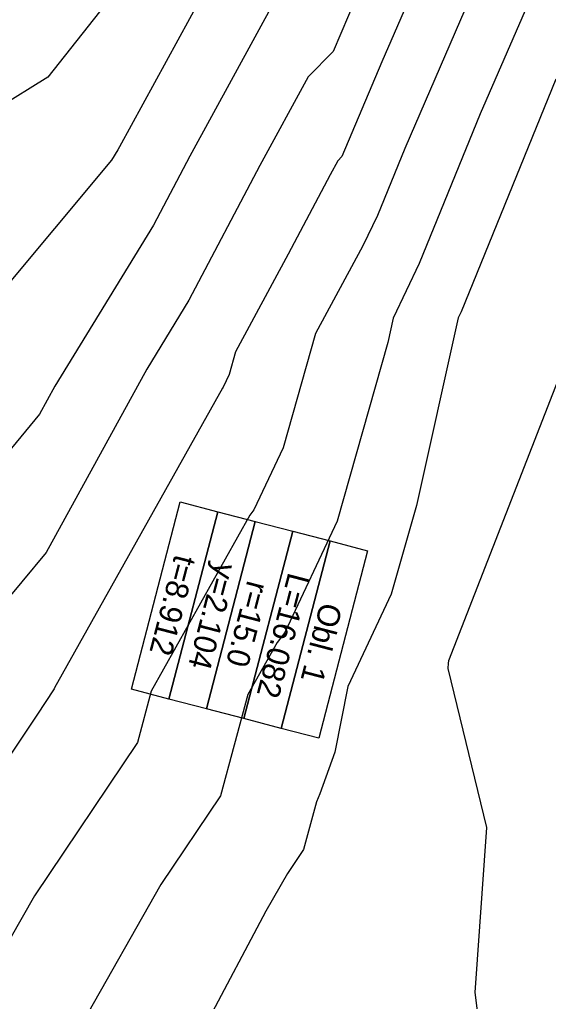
# Model space of a CAD drawing. Extents: x -549394 to -546608, y -1037055 to -1033629.
# Drawn here: x -547815.5 to -547733.5, y -1034670.8 to -1034518.7 of the extents above; entities that cross this region are included whole.
import ezdxf

# ---------------------------------------------------------------- set-up
doc = ezdxf.new("R2010")
doc.units = 0
for name, color, linetype in [('hlavni_vrst', 7, 'Continuous'), ('norm_vrst', 7, 'Continuous'), ('x_popis_oblouky_C211', 7, 'Continuous')]:
    doc.layers.add(name, color=color, linetype=linetype)

msp = doc.modelspace()

# ---------------------------------------------------------------- linework, layer by layer
at = {"layer": 'hlavni_vrst'}
for p, q in [((-547737, -1034495.44), (-547755.79, -1034538.71)), ((-547793.79, -1034505.78), (-547811.09, -1034527.65)), ((-547811.09, -1034527.65), (-547820.62, -1034533.57)), ((-547755.79, -1034538.71), (-547760.02, -1034549.09)), ((-547760.02, -1034549.09), (-547762.25, -1034553.76)), ((-547762.25, -1034553.76), (-547769.61, -1034567.38)), ((-547769.61, -1034567.38), (-547774.62, -1034585.07)), ((-547774.62, -1034585.07), (-547779.14, -1034594.65)), ((-547779.14, -1034594.65), (-547779.8, -1034595.52)), ((-547779.8, -1034595.52), (-547795.06, -1034622.76)), ((-547795.06, -1034622.76), (-547797.21, -1034630.7)), ((-547797.21, -1034630.7), (-547813.16, -1034654.45)), ((-547813.16, -1034654.45), (-547828.03, -1034680.56))]:
    msp.add_line(p, q, dxfattribs=at)
at = {"layer": 'norm_vrst'}
for p, q in [((-547747.6, -1034478.05), (-547766.85, -1034523.7)), ((-547741.45, -1034484.11), (-547759.32, -1034525.27)), ((-547779.89, -1034501.69), (-547799.97, -1034538.43)), ((-547732.55, -1034506.77), (-547744.08, -1034533.33)), ((-547775.31, -1034514.66), (-547789.09, -1034539.88)), ((-547766.85, -1034523.7), (-547770.72, -1034527.63)), ((-547759.32, -1034525.27), (-547765.52, -1034539.97)), ((-547770.72, -1034527.63), (-547778.21, -1034541.33)), ((-547732.38, -1034527.95), (-547747.04, -1034563.99)), ((-547744.08, -1034533.33), (-547753.53, -1034556.54)), ((-547799.97, -1034538.43), (-547800.23, -1034538.94)), ((-547800.23, -1034538.94), (-547801.2, -1034540.52)), ((-547789.09, -1034539.88), (-547794.73, -1034550.56)), ((-547765.52, -1034539.97), (-547766.14, -1034540.6)), ((-547801.2, -1034540.52), (-547820.19, -1034563.23)), ((-547778.21, -1034541.33), (-547789.22, -1034562.18)), ((-547766.14, -1034540.6), (-547767.34, -1034542.78)), ((-547767.34, -1034542.78), (-547773.83, -1034555.08)), ((-547794.73, -1034550.56), (-547809.98, -1034575.52)), ((-547773.83, -1034555.08), (-547781.99, -1034570.2)), ((-547753.53, -1034556.54), (-547757.57, -1034564.98)), ((-547789.22, -1034562.18), (-547795.76, -1034572.88)), ((-547727.2, -1034562.14), (-547749.02, -1034618.05)), ((-547747.04, -1034563.99), (-547747.51, -1034564.96)), ((-547757.57, -1034564.98), (-547758.41, -1034568.77)), ((-547747.51, -1034564.96), (-547753.98, -1034594)), ((-547758.41, -1034568.77), (-547766.25, -1034596.41)), ((-547781.99, -1034570.2), (-547783, -1034573.73)), ((-547795.76, -1034572.88), (-547811.34, -1034601.27)), ((-547783, -1034573.73), (-547783.9, -1034575.65)), ((-547809.98, -1034575.52), (-547812.36, -1034579.85)), ((-547784.03, -1034575.82), (-547810.04, -1034622.26)), ((-547783.9, -1034575.65), (-547784.03, -1034575.82)), ((-547812.36, -1034579.85), (-547833.3, -1034605.08)), ((-547753.98, -1034594), (-547757.88, -1034607.75)), ((-547766.25, -1034596.41), (-547774.38, -1034613.65)), ((-547811.34, -1034601.27), (-547821.7, -1034613.75)), ((-547757.88, -1034607.75), (-547764.62, -1034622.04)), ((-547774.38, -1034613.65), (-547775.57, -1034615.21)), ((-547775.57, -1034615.21), (-547780.08, -1034623.27)), ((-547749.07, -1034618.45), (-547749.08, -1034619.24)), ((-547749.08, -1034619.24), (-547743.1, -1034643.88)), ((-547749.02, -1034618.05), (-547749.07, -1034618.45)), ((-547810.04, -1034622.26), (-547810.08, -1034622.42)), ((-547764.62, -1034622.04), (-547766.61, -1034632.23)), ((-547810.08, -1034622.42), (-547812.8, -1034626.46)), ((-547780.08, -1034623.27), (-547784.33, -1034638.99)), ((-547812.8, -1034626.46), (-547830.92, -1034653.55)), ((-547766.61, -1034632.23), (-547768.96, -1034638.67)), ((-547784.33, -1034638.99), (-547793.55, -1034652.72)), ((-547768.96, -1034638.67), (-547769.46, -1034639.88)), ((-547769.46, -1034639.88), (-547771.45, -1034647.27)), ((-547743.1, -1034643.88), (-547744.93, -1034669.44)), ((-547771.45, -1034647.27), (-547773.94, -1034650.98)), ((-547773.94, -1034650.98), (-547777.29, -1034656.86)), ((-547793.55, -1034652.72), (-547805.95, -1034674.5)), ((-547777.29, -1034656.86), (-547787.97, -1034676.96)), ((-547744.93, -1034669.44), (-547743.38, -1034681))]:
    msp.add_line(p, q, dxfattribs=at)
at = {"layer": 'x_popis_oblouky_C211'}
for points in [[(-547784.75, -1034594.96), (-547792.32, -1034623.99), (-547798.13, -1034622.47), (-547790.56, -1034593.44)], [(-547778.94, -1034596.47), (-547786.52, -1034625.5), (-547792.32, -1034623.99), (-547784.75, -1034594.96)], [(-547773.14, -1034597.99), (-547780.71, -1034627.01), (-547786.52, -1034625.5), (-547778.94, -1034596.47)], [(-547767.33, -1034599.5), (-547774.91, -1034628.53), (-547780.71, -1034627.01), (-547773.14, -1034597.99)], [(-547761.53, -1034601.02), (-547769.1, -1034630.04), (-547774.91, -1034628.53), (-547767.33, -1034599.5)]]:
    msp.add_lwpolyline(points, close=True, dxfattribs=at)

# ---------------------------------------------------------------- texts
for s, p in [('t=8.912', (-547791.4, -1034601.44)), ('y=2.104', (-547785.13, -1034602.6)), ('L=16.082', (-547773.79, -1034604.23)), ('r=15.0', (-547780.14, -1034605.47)), ('Obl. 1', (-547768.79, -1034608.85))]:
    msp.add_text(s, height=3.5, rotation=255.401, dxfattribs=at).set_placement(p)

doc.saveas('drawing.dxf')
